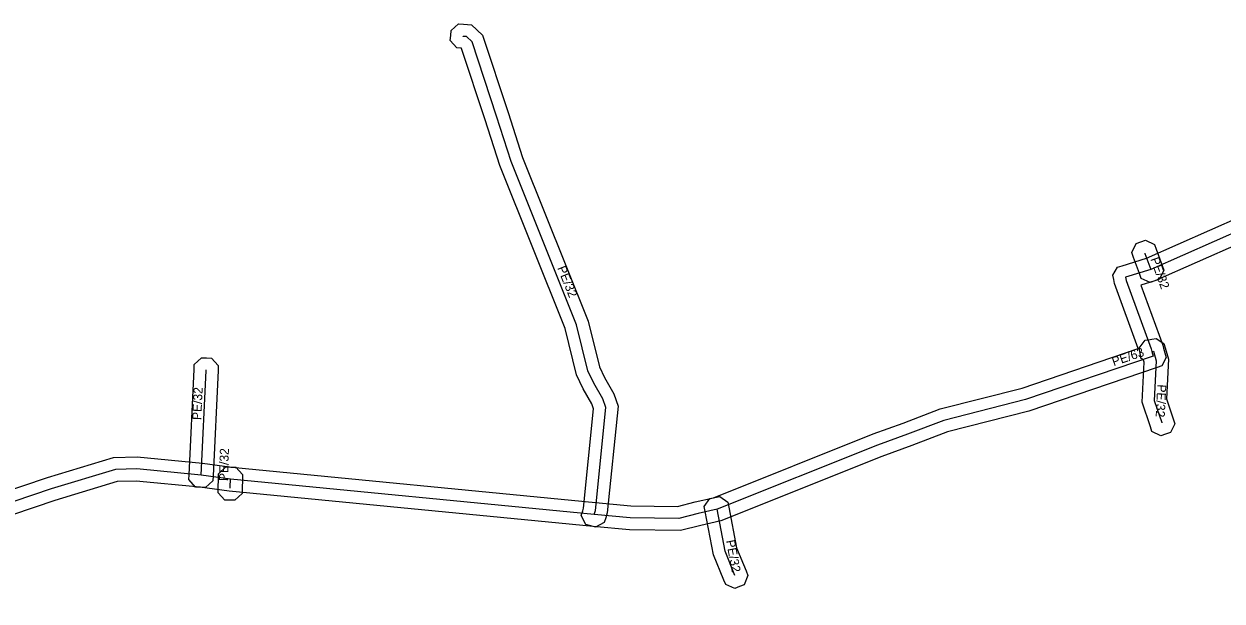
# Model space of a CAD drawing. Extents: x -677728 to -676939, y -1057290 to -1056960.
# Drawn here: x -677628.5 to -677528.9, y -1057265 to -1057217.1 of the extents above; entities that cross this region are included whole.
import ezdxf

# ---------------------------------------------------------------- set-up
doc = ezdxf.new("R2010")
doc.units = 0
for name, color, linetype in [('1', 7, 'Continuous'), ('24', 7, 'Continuous'), ('30', 7, 'Continuous')]:
    doc.layers.add(name, color=color, linetype=linetype)

msp = doc.modelspace()

# ---------------------------------------------------------------- linework, layer by layer
at = {"layer": '1'}
for points in [[(-677592.1, -1057219.106), (-677592.117, -1057219.09), (-677592.496, -1057219.062), (-677593.036, -1057218.434), (-677593.005, -1057218.021), (-677592.974, -1057217.608), (-677592.346, -1057217.068), (-677591.933, -1057217.099), (-677591.264, -1057217.149), (-677590.36, -1057217.994), (-677588.239, -1057224.422), (-677587.048, -1057228.162), (-677581.586, -1057241.773), (-677580.652, -1057245.556), (-677580.234, -1057246.454), (-677579.436, -1057247.812), (-677579.093, -1057248.825), (-677579.995, -1057257.687), (-677580.123, -1057258.11), (-677580.243, -1057258.506), (-677580.974, -1057258.897), (-677581.37, -1057258.777), (-677581.766, -1057258.657), (-677582.157, -1057257.926), (-677582.037, -1057257.53), (-677581.965, -1057257.293), (-677581.127, -1057249.055), (-677581.264, -1057248.648), (-677582.006, -1057247.386), (-677582.548, -1057246.224), (-677583.494, -1057242.387), (-677588.932, -1057228.838), (-677590.141, -1057225.038)], [(-677534.524, -1057235.399), (-677534.384, -1057235.789), (-677533.899, -1057237.143), (-677533.759, -1057237.533), (-677534.113, -1057238.281), (-677534.503, -1057238.421), (-677534.893, -1057238.561), (-677535.641, -1057238.207), (-677535.781, -1057237.817), (-677536.266, -1057236.463), (-677536.406, -1057236.073), (-677536.052, -1057235.325), (-677535.662, -1057235.185), (-677535.272, -1057235.045)], [(-677535.387, -1057245.167), (-677535.432, -1057245.012), (-677535.665, -1057244.841), (-677535.728, -1057244.432), (-677535.791, -1057244.023), (-677535.301, -1057243.355), (-677534.892, -1057243.292), (-677534.762, -1057243.272), (-677534.39, -1057243.214), (-677533.755, -1057243.619), (-677533.65, -1057243.98), (-677533.373, -1057244.933), (-677533.542, -1057248.22), (-677532.975, -1057249.894), (-677532.842, -1057250.287), (-677533.209, -1057251.029), (-677533.601, -1057251.162), (-677533.994, -1057251.295), (-677534.736, -1057250.928), (-677534.869, -1057250.536), (-677535.558, -1057248.5)], [(-677614.758, -1057254.937), (-677614.739, -1057254.523), (-677614.327, -1057245.776), (-677614.308, -1057245.362), (-677613.695, -1057244.805), (-677613.281, -1057244.824), (-677612.867, -1057244.843), (-677612.31, -1057245.456), (-677612.329, -1057245.87), (-677612.741, -1057254.617), (-677612.76, -1057255.031), (-677613.373, -1057255.588), (-677613.787, -1057255.569), (-677614.201, -1057255.55)], [(-677612.335, -1057256.024), (-677612.323, -1057255.61), (-677612.3, -1057254.859), (-677612.287, -1057254.445), (-677611.683, -1057253.878), (-677611.269, -1057253.89), (-677610.855, -1057253.903), (-677610.288, -1057254.507), (-677610.3, -1057254.921), (-677610.323, -1057255.672), (-677610.336, -1057256.086), (-677610.94, -1057256.653), (-677611.354, -1057256.641), (-677611.768, -1057256.628)], [(-677570.155, -1057263.66), (-677570.312, -1057263.276), (-677571.174, -1057261.176), (-677571.853, -1057257.586), (-677571.93, -1057257.179), (-677571.463, -1057256.494), (-677571.056, -1057256.417), (-677570.649, -1057256.34), (-677569.964, -1057256.807), (-677569.887, -1057257.214), (-677569.246, -1057260.604), (-677568.462, -1057262.518), (-677568.305, -1057262.901), (-677568.624, -1057263.665), (-677569.008, -1057263.822), (-677569.391, -1057263.979)]]:
    msp.add_lwpolyline(points, close=True, dxfattribs=at)
for points in [[(-677651.28, -1057263.136), (-677626.516, -1057254.758), (-677621.017, -1057253.083), (-677619.05, -1057253.049), (-677613.627, -1057253.576), (-677611.187, -1057253.896), (-677580.985, -1057256.824), (-677578.026, -1057257.101), (-677574.157, -1057257.158), (-677572.683, -1057256.787), (-677571.169, -1057256.442), (-677557.896, -1057251.135), (-677555.399, -1057250.233), (-677552.324, -1057249.055), (-677545.535, -1057247.321), (-677535.874, -1057244.036), (-677537.847, -1057238.648), (-677537.912, -1057238.309), (-677537.985, -1057237.933), (-677537.589, -1057237.276), (-677537.223, -1057237.164), (-677535.19, -1057236.541), (-677524.674, -1057231.888)], [(-677523.946, -1057233.752), (-677534.49, -1057238.419), (-677535.668, -1057238.78), (-677533.846, -1057243.756), (-677533.776, -1057244.013), (-677533.668, -1057244.399), (-677533.56, -1057244.783), (-677533.93, -1057245.489), (-677534.308, -1057245.617), (-677544.965, -1057249.239), (-677551.716, -1057250.965), (-677554.701, -1057252.107), (-677557.184, -1057253.005), (-677570.571, -1057258.358), (-677572.217, -1057258.733), (-677573.923, -1057259.162), (-677578.134, -1057259.099), (-677581.175, -1057258.816), (-677611.413, -1057255.884), (-677613.853, -1057255.564), (-677619.13, -1057255.051), (-677620.703, -1057255.077), (-677625.904, -1057256.662), (-677650.62, -1057265.024)]]:
    msp.add_lwpolyline(points, dxfattribs=at)
at = {"layer": '24'}
for points in [[(-677581.08, -1057257.82), (-677580.98, -1057257.49), (-677580.11, -1057248.94), (-677580.35, -1057248.23), (-677581.12, -1057246.92), (-677581.6, -1057245.89), (-677582.54, -1057242.08), (-677587.99, -1057228.5), (-677589.19, -1057224.73), (-677591.23, -1057218.55), (-677591.69, -1057218.12), (-677591.96, -1057218.1), (-677592.008, -1057218.096)], [(-677524.31, -1057232.82), (-677534.84, -1057237.48), (-677536.93, -1057238.12), (-677536.88, -1057238.38), (-677534.8, -1057244.06), (-677534.74, -1057244.28), (-677534.63, -1057244.67), (-677545.25, -1057248.28), (-677552.02, -1057250.01), (-677555.05, -1057251.17), (-677557.54, -1057252.07), (-677570.87, -1057257.4), (-677572.45, -1057257.76), (-677574.04, -1057258.16), (-677578.08, -1057258.1), (-677581.08, -1057257.82), (-677611.3, -1057254.89), (-677613.74, -1057254.57), (-677619.09, -1057254.05), (-677620.86, -1057254.08), (-677626.21, -1057255.71), (-677650.95, -1057264.08)], [(-677535.325, -1057236.126), (-677535.32, -1057236.14), (-677534.84, -1057237.48)], [(-677534.74, -1057244.28), (-677534.61, -1057244.26), (-677534.38, -1057245.05), (-677534.55, -1057248.36), (-677533.93, -1057250.19), (-677533.922, -1057250.215)], [(-677613.74, -1057254.57), (-677613.33, -1057245.86), (-677613.328, -1057245.823)], [(-677611.323, -1057255.641), (-677611.32, -1057255.53), (-677611.3, -1057254.89)], [(-677569.387, -1057262.897), (-677570.21, -1057260.89), (-677570.87, -1057257.4)]]:
    msp.add_lwpolyline(points, dxfattribs=at)

# ---------------------------------------------------------------- texts
at = {"layer": '30'}
for s, rotation, p in [('PE/32', 291.86685, (-677584.161, -1057237.343)), ('PE/32', 289.70798, (-677534.883, -1057236.603)), ('PE/63', 18.77416, (-677537.913, -1057245.518)), ('PE/32', 267.0599, (-677534.291, -1057247.006)), ('PE/32', 87.30494, (-677613.734, -1057249.996)), ('PE/32', 88.21009, (-677611.512, -1057255.065)), ('PE/32', 280.70884, (-677570.138, -1057260.011))]:
    msp.add_text(s, height=0.75, rotation=rotation, dxfattribs=at).set_placement(p)

doc.saveas('drawing.dxf')
